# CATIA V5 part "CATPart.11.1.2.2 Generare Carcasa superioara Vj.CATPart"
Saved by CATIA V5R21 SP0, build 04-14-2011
Part number: Carcasa superioara vJ
Bounding box of the stored display mesh (mm): x -108.5 to 26.5, y -240 to 0, z 0 to 102
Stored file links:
  C:\Users\MIRCEA\Desktop\MOM\Mogan\model\CATPart.11.1.2.2 Generare Carcasa superioara Vj.CATPart
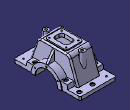
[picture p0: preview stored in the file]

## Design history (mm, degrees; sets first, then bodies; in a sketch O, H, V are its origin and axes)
Parameters
  Hg = 90 mm
  Lg = 66 mm
  L1 = 88 mm
  L2 = 75 mm
  Rf2 = 55 mm
  Rr2 = 40 mm
  Lf = 32 mm
  gp = 8 mm
  gf = 12 mm
  gf2 = 15 mm
AxisSystem1: origin (0, 0, 0), X (1, 0, 0), Y (0, 1, 0), Z (0, 0, 1)
Sketch1 on face of Pad4 from Sketch4.L3, origin (0, 0, 98), H (1, 0, 0), V (0, 1, 0)
  point P1 (-38, -120.5778)
  line L1 (-7, -91.1555) -> (-7, -150)
  line L2 (-17, -160) -> (-59, -160)
  line L3 (-69, -150) -> (-69, -91.1555)
  line L4 (-59, -81.1555) -> (-17, -81.1555)
  point P2 (-69, -160)
  arc A1 centre (-17, -91.1555) radius 10 from (-17, -81.1555) to (-7, -91.1555) cw
  arc A2 centre (-59, -91.1555) radius 10 from (-59, -81.1555) to (-69, -91.1555) ccw
  arc A3 centre (-59, -150) radius 10 from (-69, -150) to (-59, -160) ccw
  arc A4 centre (-17, -150) radius 10 from (-7, -150) to (-17, -160) cw
  distance P2 H = 160
  distance P2 V = 69
  radius A1 = 10
  radius A2 = 10
  radius A3 = 10
  radius A4 = 10
  distance L3 L1 = 62
  vertical: L1 V, L3 V
  horizontal: L2 H, L4 H
  equidistance: L1 L3 P1, L2 L4 P1
  tangency: A1 L4, A1 L1, A2 L4, A2 L3, A3 L3, A3 L2, A4 L1, A4 L2
  coincidence: L3 P2, L2 P2
Pad1: profile Sketch1, direction (0, 0, 1), length 4
Set1
  Sketch2 on YZ plane of AxisSystem1, origin (0, 0, 0), H (0, 1, 0), V (0, 0, 1)
    arc A1 centre (-120, 0) radius 40 from (-80, 0) to (-160, 0) ccw
    point P1 (-120, 0)
    arc A2 centre (-120, 0) radius 55 from (-66.3251, 12) to (-173.6749, 12) ccw
    line L1 (0, 0) -> (-80, 0)
    line L2 (-240, 0) -> (-240, 12)
    line L3 (-240, 12) -> (-173.6749, 12)
    line L4 (0, 12) -> (0, 0)
    point P5 (-160, 0)
    line L5 (-160, 0) -> (-240, 0)
    line L6 (-66.3251, 12) -> (0, 12)
    reference projected line E1 through (0, 0) direction (0, 1) from edge [ZX plane of AxisSystem1 | YZ plane of AxisSystem1]
    reference intersected line E2 through (0, 0) direction (0, 1) from ZX plane of AxisSystem1
    distance P1 E2 = 120 {= L1 +Lf}
    radius A1 = 40 {= Rr2}
    radius A2 = 55 {= Rf2}
    length L2 = 12 {= gf}
    coincidence: P1 H, L1 P5, L1 L5, L3 L6
    horizontal: L1 H, L3 H, L5 H, L6 H
    vertical: L2 V, L4 V
    equidistance: L2 E1 P1
Body1 (main body)
  Pad2 "Suport rulmenti": profile Sketch2, direction (1, 0, 0), length 24 {= Lf -gp}
  Sketch3 on start face of Pad2, origin (0, 0, 0), H (0, -1, 0), V (0, 0, 1)
    arc A1 centre (120, 0) radius 40 from (160, 0) to (80, 0) ccw
    point P1 (120, 0)
    reference projected arc E1 centre (120, 0) radius 40 from (160, 0) to (80, 0) ccw from edge [start face of Pad2 | face of Pad2 from Sketch2.A1]
    line L1 (80, 0) -> (32, 0)
    line L2 (32, 0) -> (64.7573, 90)
    line L3 (64.7573, 90) -> (175.2427, 90)
    line L4 (175.2427, 90) -> (208, 0)
    point P6 (208, 0)
    line L5 (208, 0) -> (160, 0)
    reference projected line E2 (240, 0) -> (160, 0) from edge [start face of Pad2 | face of Pad2 from Sketch2.L5]
    angle L4 L5 = 70
    angle L2 L1 = 70
    distance L5 L3 = 90 {= Hg}
    distance P6 P1 = 88 {= L1}
    coincidence: A1 E1, P6 L1, L5 E2
    horizontal: L1 H, L3 H, L5 H
    equidistance: L4 L2 P1
  Pad3 "Perete lateral": profile Sketch3, direction (-1, 0, 0), length 8 {= gp}
  Plane1: type Offset, RefPlane end face of Pad3, Offset 33 {= Lg/2}, reversed
  Plane2: type Offset, RefPlane ZX plane of AxisSystem1, Offset 120 {= L1 +Lf}, reversed
  Mirror1: of the body so far, about Plane1
  Sketch4 on start face of Pad2, origin (0, 0, 0), H (0, -1, 0), V (0, 0, 1)
    line L1 (0, 12) -> (32, 12)
    line L2 (32, 12) -> (63.3014, 98)
    line L3 (63.3014, 98) -> (176.6986, 98)
    line L4 (176.6986, 98) -> (208, 12)
    point P5 (208, 12)
    line L5 (208, 12) -> (240, 12)
    line L6 (240, 12) -> (240, 0)
    line L7 (240, 0) -> (208, 0)
    point P8 (208, 0)
    projected line E1 (203.6324, 12) -> (175.2427, 90) from edge [start face of Pad3 | face of Pad3 from Sketch3.L4]
    projected line E2 (208, 0) -> (203.6324, 12) from edge [start face of Pad2 | face of Pad3 from Sketch3.L4]
    point P11 (208, 0)
    projected line E3 (175.2427, 90) -> (64.7573, 90) from edge [start face of Pad3 | face of Pad3 from Sketch3.L3]
    projected line E4 (64.7573, 90) -> (36.3676, 12) from edge [start face of Pad3 | face of Pad3 from Sketch3.L2]
    projected line E5 (36.3676, 12) -> (32, 0) from edge [start face of Pad2 | face of Pad3 from Sketch3.L2]
    point P18 (32, 0)
    reference projected line E6 (240, 12) -> (240, 0) from edge [start face of Pad2 | face of Pad2 from Sketch2.L2]
    reference projected line E7 (173.6749, 12) -> (240, 12) from edge [start face of Pad2 | face of Pad2 from Sketch2.L3]
    line L8 (0, 12) -> (0, 0)
    line L9 (0, 0) -> (32, 0)
    point P20 (32, 0)
    reference projected line E8 (80, 0) -> (0, 0) from edge [start face of Pad2 | face of Pad3]
    reference intersected line E9 through (0, 0) direction (0, -1) from ZX plane of AxisSystem1
    distance E3 L3 = 8 {= gp}
    length L1 = 32 {= Lf}
    length L5 = 32 {= Lf}
    horizontal: L1 H, L3 H, L5 H, L7 H
    coincidence: P5 L1, P8 P11, L6 E6, L5 E7, P18 P20, E8 L9, L8 E9
    vertical: L8 V
    parallelism: E4 L2, E1 L4
  Pad4 "Capac": profile Sketch4, direction (-1, 0, 0), length 82 {= Lg+2*gp}
  Sketch5 on face of Pad4, origin (0, 0, 0), H (0, 1, 0), V (0, 0, 1)
    arc A1 centre (-120, 0) radius 55 from (-66.3251, 12) to (-72.0834, 27) ccw
    point P1 (-120, 0)
    reference projected arc E1 centre (-120, 0) radius 55 from (-66.3752, 12.2222) to (-173.6248, 12.2222) ccw from edge [face of Pad2 from Sketch2.A2 | end face of Pad2]
    line L1 (-195, 12) -> (-173.6749, 12)
    point P3 (-45, 12)
    reference projected line E2 (0, 12) -> (-66.3251, 12) from edge [face of Pad4 | end face of Pad2]
    line L2 (-45, 12) -> (-46.8418, 27)
    line L3 (-46.8418, 27) -> (-72.0834, 27)
    line L4 (-193.1582, 27) -> (-195, 12)
    point P7 (-66.3251, 12)
    line L5 (-66.3251, 12) -> (-45, 12)
    line L6 (-167.9166, 27) -> (-193.1582, 27)
    point P9 (-167.9166, 27)
    arc A2 centre (-120, 0) radius 55 from (-167.9166, 27) to (-173.6749, 12) ccw
    distance L3 L1 = 15 {= gf2}
    angle L3 L2 = 83
    angle L3 L4 = 83
    distance P3 V = 45 {= L1 +Lf - L2}
    coincidence: A1 E1, L1 E2, L1 P7, L1 L5, A1 P9, L3 L6, A1 A2
    horizontal: L1 H, L5 H
    equidistance: L2 L4 P1
  Pad5 "Intaritura": profile Sketch5, direction (1, 0, 0), length 24 {= Lf -gp}
  Mirror2: of Pad5, about Plane1
  Sketch6 on face of Pad5, origin (24, 0, 0), H (0, 1, 0), V (0, 0, 1)
    arc A1 centre (-120, 0) radius 40 from (-80, 0) to (-160, 0) ccw
    arc A2 centre (-120, 0) radius 55 from (-65, 0) to (-175, 0) ccw
    reference projected arc E1 centre (-120, 0) radius 55 from (-66.3752, 12.2222) to (-173.6248, 12.2222) ccw from edge [face of Pad2 from Sketch2.A2 | face of Pad5]
    reference projected arc E2 centre (-120, 0) radius 40 from (-80, 0) to (-160, 0) ccw from edge [face of Pad3 | face of Pad5]
    line L1 (-175, 0) -> (-160, 0)
    reference projected line E3 (-80, 0) -> (0, 0) from edge [face of Pad4 | face of Pad5]
    reference projected line E4 (-240, 0) -> (-160, 0) from edge [face of Pad4 | face of Pad5]
    point P5 (-80, 0)
    line L2 (-80, 0) -> (-65, 0)
    coincidence: A2 E1, A1 E2, L1 E3, L1 E4, L1 P5, L1 L2
    horizontal: L1 H, L2 H
  Pad6: profile Sketch6, direction (1, 0, 0), length 2.5
  Sketch7 on face of Mirror2, origin (-106, 0, 0), H (0, -1, 0), V (0, 0, 1)
    arc A1 centre (120, 0) radius 40 from (160, 0) to (80, 0) ccw
    arc A2 centre (120, 0) radius 55 from (175, 0) to (65, 0) ccw
    reference projected arc E1 centre (120, 0) radius 55 from (173.6248, 12.2222) to (66.3752, 12.2222) ccw from edge [face of Mirror2 | face of Mirror1]
    reference projected arc E2 centre (120, 0) radius 40 from (160, 0) to (80, 0) ccw from edge [face of Mirror1 | face of Mirror1]
    line L1 (65, 0) -> (80, 0)
    reference projected line E3 (240, 0) -> (160, 0) from edge [face of Mirror2 | face of Pad6]
    point P5 (160, 0)
    line L2 (160, 0) -> (175, 0)
    coincidence: A2 E1, A1 E2, E3 L1, L1 P5, L1 L2
    horizontal: L1 H, L2 H
  Pad7: profile Sketch7, direction (-1, 0, 0), length 2.5
  Sketch8 on Plane2, origin (0, -120, 0), H (-1, 0, 0), V (0, 0, 1)
    point P1 (-24, 55)
    line L1 (-24, 55) -> (0, 89)
    point P2 (0, 89)
    point P3 (0, 80)
    reference intersected line E1 through (0, 0) direction (0, -1) from yz-plane
    reference intersected line E2 through (0, 0) direction (-1, 0) from xy-plane
    reference intersected line E3 through (0, 0) direction (-1, 0) from xy-plane
    reference intersected line E4 through (0, 0) direction (0, -1) from yz-plane
    distance P2 E1 = 0
    distance P2 E2 = 89 {= Hg +gp-9mm}
    distance P1 E3 = 55 {= Rf2}
    distance P1 E4 = 24 {= Lf -gp}
  Stiffener1: ExtendedProfile Sketch8, ThicknessTop 0, ThicknessValue 8 {= gp}
  Mirror3: of Stiffener1, about Plane1
  Fillet1: radius 15, on edge [face of Pad4 from Sketch4.L3 | face of Pad4 from Sketch4.L4]; edge [face of Pad4 from Sketch4.L2 | face of Pad4 from Sketch4.L3]
  Plane3: type Offset, RefPlane xy-plane, Offset 100
  Sketch9 on Plane3, origin (0, 0, 100), H (1, 0, 0), V (0, 1, 0)
    circle A1 centre (-38, -55) radius 10
    circle A2 centre (-38, -185) radius 10
    radius A1 = 10
    radius A2 = 10
  Pad8: profile Sketch9, direction (0, 0, -1), up to the existing solid (limit type 2)
  DatumCurve1
  DatumCurve2
  Sketch10 on end face of Pad1, origin (0, 0, 102), H (1, 0, 0), V (0, 1, 0)
    point P1 (-38, -120.578)
    line L1 (-21, -105.156) -> (-21, -136)
    line L2 (-31, -146) -> (-45, -146)
    line L3 (-55, -136) -> (-55, -105.156)
    line L4 (-45, -95.156) -> (-31, -95.156)
    arc A1 centre (-31, -105.156) radius 10 from (-31, -95.156) to (-21, -105.156) cw
    arc A2 centre (-45, -105.156) radius 10 from (-45, -95.156) to (-55, -105.156) ccw
    arc A3 centre (-45, -136) radius 10 from (-55, -136) to (-45, -146) ccw
    arc A4 centre (-31, -136) radius 10 from (-31, -146) to (-21, -136) ccw
    reference projected line E1 (-31, -146) -> (-45, -146) from edge of DatumCurve1
    reference projected line E2 (-45, -95.156) -> (-31, -95.156) from edge of DatumCurve2
    radius A1 = 10
    radius A2 = 10
    radius A3 = 10
    radius A4 = 10
    distance E1 L2 = 0
    distance L4 E2 = 0
    vertical: L1 V, L3 V
    horizontal: L2 H, L4 H
    equidistance: L1 L3 P1, L2 L4 P1
    tangency: A1 L4, A1 L1, A2 L4, A2 L3, A3 L3, A3 L2, A4 L2, A4 L1
  Pocket1: profile Sketch10, direction (0, 0, -1), through (limit type 6)
  Plane4: type Offset, RefPlane xy-plane, Offset 27
  DatumCurve3 to DatumCurve5
  Sketch11 on Plane4, origin (0, 0, 27), H (1, 0, 0), V (0, 1, 0)
    point P1 (-88.5, -60)
    point P2 (-88.5, -180)
    point P3 (6.5, -180)
    reference projected point E1 (6.5, -180) from edge of DatumCurve3
    reference projected point E2 (-88.5, -180) from edge of DatumCurve4
    reference projected point E3 (-88.5, -60) from edge of DatumCurve5
    distance P3 E1 = 0
    distance P2 E2 = 0
    distance P1 E3 = 0
  DatumCurve6 to DatumCurve8
  Sketch12 on Plane4, origin (0, 0, 27), H (1, 0, 0), V (0, 1, 0)
    point P1 (12, -65)
    reference projected point E1 (12, -65) from edge of DatumCurve8
    distance P1 E1 = 0
  Plane5: type Offset, RefPlane xy-plane, Offset 12
  Sketch13 on Plane5, origin (0, 0, 12), H (1, 0, 0), V (0, 1, 0)
    point P1 (9.5, -17.5)
    point P2 (-38, -222.5)
    point P3 (-85.5, -222.5)
  Sketch14 on Plane5, origin (0, 0, 12), H (1, 0, 0), V (0, 1, 0)
    point P1 (-38, -17.5)
  Sketch15 on face of Pad4, origin (0, -17.5, 12), H (1, 0, 0), V (0, 1, 0)
    point P1 (-38, 0)
    reference projected point E1 (-38, 0) from Sketch14.P1
    coincidence: E1 P1
  Hole1: placed by Sketch15, at (-38, -17.5, 12) direction (0, 0, -1), diameter 10, through (limit type 6), counterbore diameter 15, counterbore depth 2
  UserPattern1: of Hole1, copies 4, at the points of Sketch13
  Sketch16 on Plane3, origin (0, 0, 100), H (1, 0, 0), V (0, 1, 0)
    circle A1 centre (-38, -55) radius 4
    point P2 (-38, -185)
    circle A2 centre (-38, -185) radius 4
    radius A1 = 4
    distance P2 H = 185
    radius A2 = 4
  Pocket2: profile Sketch16, direction (0, 0, -1), through (limit type 6)
  Sketch17 on end face of Pad1, origin (0, 0, 102), H (1, 0, 0), V (0, 1, 0)
    point P1 (-60, -90.1555)
    point P2 (-60, -90.1555)
    point P3 (-60, -151)
    point P4 (-16, -151)
    reference projected line E1 (-17, -81.1555) -> (-59, -81.1555) from edge [face of Pad1 from Sketch1.L4 | end face of Pad1]
    reference projected line E2 (-69, -91.1555) -> (-69, -150) from edge [face of Pad1 from Sketch1.L3 | end face of Pad1]
    reference projected line E3 (-69, -91.1555) -> (-69, -150) from edge [face of Pad1 from Sketch1.L3 | end face of Pad1]
    reference projected line E4 (-59, -160) -> (-17, -160) from edge [face of Pad1 from Sketch1.L2 | end face of Pad1]
    reference projected line E5 (-59, -160) -> (-17, -160) from edge [face of Pad1 from Sketch1.L2 | end face of Pad1]
    reference projected line E6 (-7, -150) -> (-7, -91.1555) from edge [face of Pad1 from Sketch1.L1 | end face of Pad1]
    distance P2 E1 = 9
    distance P2 E2 = 9
    distance P3 E3 = 9
    distance P3 E4 = 9
    distance P4 E5 = 9
    distance P4 E6 = 9
    coincidence: P2 P1
  Sketch18 on end face of Pad1, origin (-15.2607, -88, 102), H (1, 0, 0), V (0, 1, 0)
    point P1 (-0.7393, -2.1555)
    reference projected line E1 (-1.7393, 6.8445) -> (-43.7393, 6.8445) from edge [face of Pad1 from Sketch1.L4 | end face of Pad1]
    reference projected line E2 (8.2607, -62) -> (8.2607, -3.1555) from edge [face of Pad1 from Sketch1.L1 | end face of Pad1]
    distance P1 E1 = 9
    distance P1 E2 = 9
  Hole2: placed by Sketch18, at (-16, -90.1555, 102) direction (0, 0, -1), diameter 5, through (limit type 6)
  UserPattern2: of Hole2, copies 4, at the points of Sketch17
  Fillet2: radius 5, on edge [face of Mirror2 | face of Pad4] (x2); edge [face of Pad4 | face of Pad5] (x2)
  Sketch19 on end face of Pad6, origin (26.5, 0, 0), H (0, 1, 0), V (0, 0, 1)
    point P1 (-153.342, 19.25)
    point P2 (-86.658, 19.25)
  Sketch20 on end face of Pad6, origin (26.5, 0, 0), H (0, 1, 0), V (0, 0, 1)
    point P1 (-120, 38.5)
  Sketch21 on end face of Pad7, origin (-108.5, 0, 0), H (0, -1, 0), V (0, 0, 1)
    point P1 (86.658, 19.25)
    point P2 (152.7211, 18.8915)
  Sketch22 on end face of Pad7, origin (-108.5, 0, 0), H (0, -1, 0), V (0, 0, 1)
    point P1 (120, 38.5)
  Chamfer1: length 1, angle 45, on edge [face of Pad7 | end face of Pad7]; edge [face of Pad6 | end face of Pad6]
  Sketch23 on end face of Pad6, origin (26.5, 0, 0), H (0, 1, 0), V (0, 0, 1)
    point P1 (-78.8638, 23.75)
    point P2 (-161.1362, 23.75)
  Sketch24 on end face of Pad6, origin (26.5, 0, 0), H (0, 1, 0), V (0, 0, 1)
    point P1 (-120, 47.5)
  Sketch25 on end face of Pad6, origin (26.5, -120, 47.5), H (0, 1, 0), V (0, 0, 1)
    point P1 (0, 0)
    reference projected point E1 (0, 0) from Sketch24.P1
    coincidence: E1 P1
  Hole3: placed by Sketch25, at (26.5, -120, 47.5) direction (-1, 0, 0), diameter 5, depth 10
  UserPattern3: of Hole3, copies 3, at the points of Sketch23
  Sketch26 on end face of Pad7, origin (-108.5, 0, 0), H (0, -1, 0), V (0, 0, 1)
    point P1 (78.8638, 23.75)
    point P2 (161.1362, 23.75)
    point P3 (78.8638, 23.75)
    coincidence: P3 P1
  Sketch27 on end face of Pad7, origin (-108.5, 0, 0), H (0, -1, 0), V (0, 0, 1)
    point P1 (120, 47.5)
  Sketch28 on end face of Pad7, origin (-108.5, -120, 47.5), H (0, 1, 0), V (0, 0, -1)
    point P1 (0, 0)
    reference projected point E1 (0, 0) from Sketch27.P1
    coincidence: E1 P1
  Hole4: placed by Sketch28, at (-108.5, -120, 47.5) direction (1, 0, 0), diameter 5, depth 10
  UserPattern4: of Hole4, copies 3, at the points of Sketch26
  Sketch29 on Plane5, origin (0, 0, 12), H (1, 0, 0), V (0, 1, 0)
    point P1 (6.5, -222.5)
    reference projected line E1 (24, -176.6749) -> (24, -246) from edge [face of Pad4 | face of Pad5]
    reference projected line E2 (0, -240) -> (27, -240) from edge [face of Pad4 | face of Pad4]
    distance P1 E1 = 17.5
    distance P1 E2 = 17.5
  Sketch30 on face of Pad4, origin (9.5, -222.5, 12), H (1, 0, 0), V (0, 1, 0)
    point P1 (-3, 0)
    reference projected point E1 (-3, 0) from Sketch29.P1
    coincidence: E1 P1
  Hole5: placed by Sketch30, at (6.5, -222.5, 12) direction (0, 0, -1), diameter 6, through (limit type 6)
  Sketch31 on Plane5, origin (0, 0, 12), H (1, 0, 0), V (0, 1, 0)
    point P1 (-88.5, -17.5)
    reference projected line E1 (24, 0) -> (0, 0) from edge [face of Pad4 | face of Pad4]
    reference projected line E2 (-106, 0) -> (-106, -69.3251) from edge [face of Mirror2 | face of Pad4]
    distance P1 E1 = 17.5
    distance P1 E2 = 17.5
  UserPattern5: of Hole5, copies 2, at the points of Sketch31
  Sketch32 on face of Pad5 from Sketch5.L3, origin (6.5, -60, 27), H (1, 0, 0), V (0, 1, 0)
    point P1 (5.5, -5)
    reference projected point E1 (5.5, -5) from Sketch12.P1
    coincidence: E1 P1
  Hole6: placed by Sketch32, at (12, -65, 27) direction (0, 0, -1), diameter 10, through (limit type 6), counterbore diameter 15, counterbore depth 4
  DatumCurve9 to DatumCurve11
  Sketch33 on face of Pad5 from Sketch5.L6, origin (0, 0, 27), H (1, 0, 0), V (0, 1, 0)
    point P1 (12, -175)
    point P2 (-94, -175)
    point P3 (-94, -65)
    reference projected point E1 (-94, -65) from edge of DatumCurve9
    reference projected point E2 (12, -175) from edge of DatumCurve10
    reference projected point E3 (-94, -175) from edge of DatumCurve11
    distance P3 E1 = 0
    distance P1 E2 = 0
    distance P2 E3 = 0
  UserPattern6: of Hole6, copies 4, at the points of Sketch33
  Fillet3: radius 5, on edge [face of Pad4 | face of Pad4 from Sketch4.L3]; edge [face of Pad4 from Sketch4.L3 | face of Pad4]
  Plane6: type Offset, RefPlane yz-plane, Offset 37 {= (Lg + gp)/2}, reversed
  Fillet4: radius 20, on edge [face of Pad4 from Sketch4.E1 | face of Pad4 from Sketch4.E3]; edge [face of Pad4 from Sketch4.E3 | face of Pad4 from Sketch4.E4]
Current feature: Fillet3
Relations
  Plane2.Offset = L1 +Lf |+gp (deactivated)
